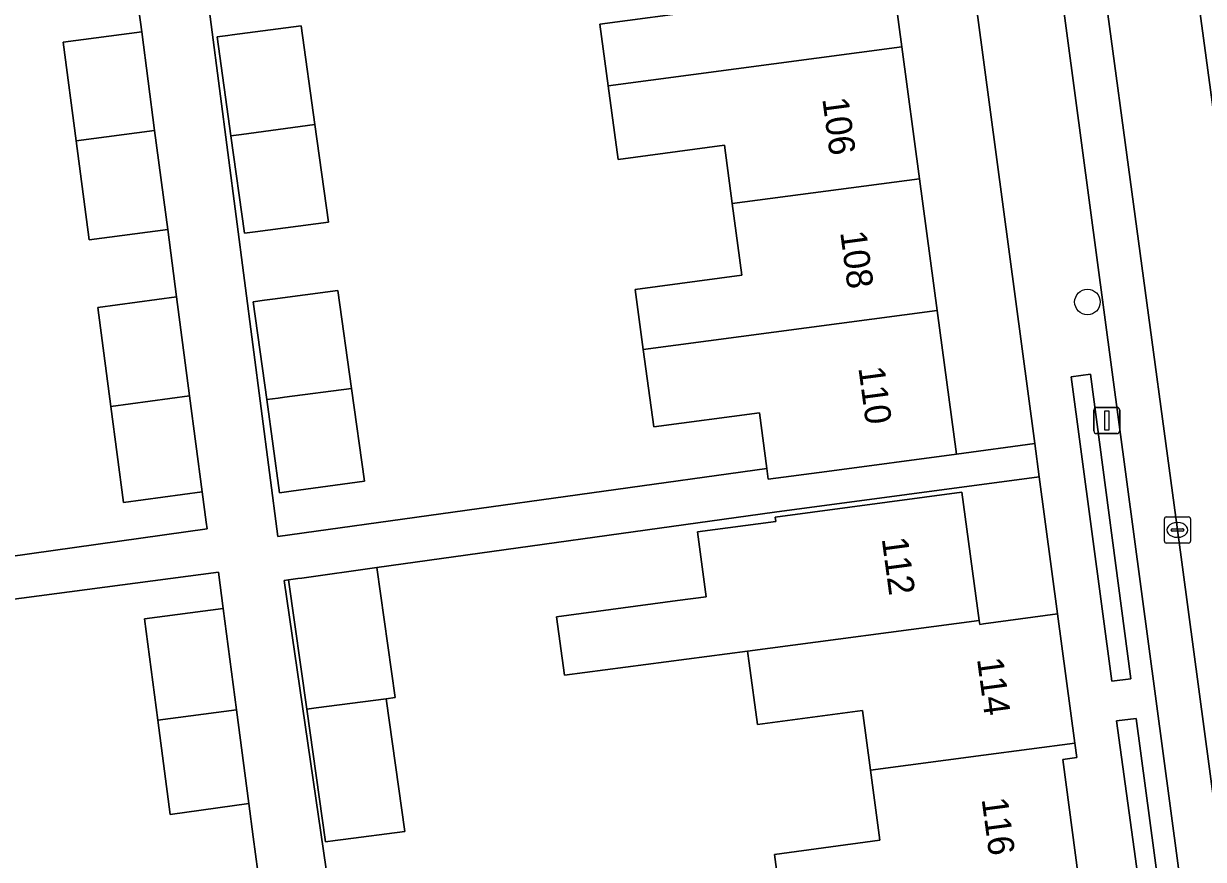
# Model space of a CAD drawing. Extents: x 163147 to 163550, y 380933 to 381639.
# Drawn here: x 163463.29 to 163508.41, y 381142.86 to 381174.85 of the extents above; entities that cross this region are included whole.
import ezdxf

# ---------------------------------------------------------------- set-up
doc = ezdxf.new("R2010")
doc.units = 0
for name, color, linetype in [('IMGEO_Boom', 7, 'Continuous'), ('IMGEO_Erf', 7, 'Continuous'), ('IMGEO_Groenvoorziening', 7, 'Continuous'), ('IMGEO_Kolk', 7, 'Continuous'), ('IMGEO_Lichtmast', 7, 'Continuous'), ('IMGEO_Pand', 7, 'Continuous'), ('IMGEO_Pand_nummerreeks', 7, 'Continuous'), ('IMGEO_Parkeervlak_open', 7, 'Continuous'), ('IMGEO_Rijbaan_lokaal_open', 7, 'Continuous'), ('IMGEO_Voetpad_open', 7, 'Continuous')]:
    doc.layers.add(name, color=color, linetype=linetype)

msp = doc.modelspace()

# ---------------------------------------------------------------- linework, layer by layer
at = {"layer": 'IMGEO_Boom'}
msp.add_circle((163503.975, 381164.194), 0.489, dxfattribs=at)
at = {"layer": 'IMGEO_Erf'}
for points in [[(163497.876, 381189.391), (163494.859, 381188.987), (163495.521, 381184.055), (163496.198, 381179.008), (163496.875, 381173.959), (163497.553, 381168.911), (163498.23, 381163.862), (163498.966, 381158.376), (163501.959, 381158.775), (163500, 381173.462)], [(163474.436, 381170.98), (163474.953, 381167.249), (163472.146, 381166.877), (163471.737, 381166.823), (163471.221, 381170.553), (163470.697, 381174.339), (163471.106, 381174.393), (163471.266, 381174.415), (163473.912, 381174.766)], [(163475.833, 381160.888), (163476.325, 381157.337), (163473.52, 381156.949), (163473.084, 381156.888), (163472.59, 381160.458), (163472.071, 381164.201), (163472.508, 381164.259), (163472.818, 381164.3), (163475.315, 381164.631)]]:
    msp.add_lwpolyline(points, close=True, dxfattribs=at)
for points in [[(163451.727, 381152.897), (163470.315, 381155.515), (163470.279, 381155.771), (163470.127, 381156.923), (163467.118, 381156.527), (163466.635, 381160.197), (163466.137, 381163.983), (163469.145, 381164.386), (163468.975, 381165.675), (163468.804, 381166.971), (163465.797, 381166.568), (163465.299, 381170.355), (163464.801, 381174.133), (163467.809, 381174.536), (163467.638, 381175.837), (163467.466, 381177.144), (163464.458, 381176.741), (163463.957, 381180.549), (163463.382, 381184.919), (163466.391, 381185.315), (163466.221, 381186.604), (163463.614, 381186.261), (163463.374, 381186.229), (163463.212, 381186.208)], [(163470.145, 381177.27), (163473.017, 381155.223), (163491.716, 381157.821), (163491.429, 381159.958), (163487.388, 381159.415), (163486.992, 381162.37), (163486.682, 381164.678), (163490.758, 381165.225), (163490.391, 381167.96), (163490.091, 381170.193), (163486.024, 381169.648), (163485.646, 381172.468), (163485.33, 381174.823), (163489.372, 381175.365)], [(163492.331, 381140.667), (163492.011, 381143.056), (163496.04, 381143.596), (163495.679, 381146.282), (163495.373, 381148.564), (163491.355, 381148.025), (163491.04, 381150.372), (163490.978, 381150.833), (163483.972, 381149.909), (163483.672, 381152.144), (163488.304, 381152.766), (163489.394, 381152.912), (163489.06, 381155.399), (163492.053, 381155.8), (163492.031, 381155.958), (163499.177, 381156.915), (163499.836, 381152.002), (163499.855, 381151.857), (163500, 381151.877), (163502.828, 381152.255), (163502.129, 381157.501), (163492.004, 381156.151), (163476.803, 381154.036), (163477.507, 381149.057), (163477.161, 381149.011), (163477.878, 381143.933), (163475.52, 381143.623), (163475.202, 381143.581), (163474.839, 381143.533), (163474.122, 381148.61), (163473.423, 381153.559), (163473.262, 381153.534), (163477.678, 381123.119)], [(163472.251, 381142.395), (163472.076, 381143.722), (163471.908, 381144.999), (163468.902, 381144.586), (163468.427, 381148.193), (163467.917, 381152.07), (163470.925, 381152.466), (163470.743, 381153.849), (163451.998, 381151.38)]]:
    msp.add_lwpolyline(points, dxfattribs=at)
at = {"layer": 'IMGEO_Groenvoorziening'}
for points in [[(163504.911, 381149.686), (163505.63, 381149.779), (163504.095, 381161.434), (163503.349, 381161.325)], [(163506.529, 381137.695), (163507.234, 381137.78), (163505.837, 381148.257), (163505.092, 381148.167)]]:
    msp.add_lwpolyline(points, close=True, dxfattribs=at)
at = {"layer": 'IMGEO_Kolk'}
for p, q in [((163506.916, 381155.044), (163506.916, 381155.896)), ((163506.991, 381155.97), (163507.843, 381155.97)), ((163507.404, 381155.75), (163507.429, 381155.75)), ((163507.917, 381155.896), (163507.917, 381155.044)), ((163507.175, 381155.464), (163507.175, 381155.476)), ((163507.613, 381155.427), (163507.215, 381155.427)), ((163507.218, 381155.513), (163507.616, 381155.513)), ((163507.427, 381155.19), (163507.402, 381155.19)), ((163507.659, 381155.476), (163507.659, 381155.464)), ((163507.843, 381154.97), (163506.991, 381154.97))]:
    msp.add_line(p, q, dxfattribs=at)
for points in [[(163506.916, 381155.044), (163506.916, 381155.896)], [(163506.991, 381155.97), (163507.843, 381155.97)], [(163507.917, 381155.896), (163507.917, 381155.044)], [(163507.843, 381154.97), (163506.991, 381154.97)]]:
    msp.add_lwpolyline(points, dxfattribs=at)
for centre, radius, start, end in [((163506.993, 381155.894), 0.0765, 91.552, 178.448), ((163506.993, 381155.894), 0.0765, 91.552, 178.448), ((163507.841, 381155.894), 0.0765, 1.552, 88.448), ((163507.841, 381155.894), 0.0765, 1.552, 88.448), ((163507.215, 381155.473), 0.0403, 85.8775, 175.7526), ((163507.212, 381155.463), 0.0366, 178.938, 274.7102), ((163507.616, 381155.47), 0.043, 264.8664, 352.4533), ((163507.62, 381155.475), 0.0386, 1.7309, 96.639), ((163506.993, 381155.046), 0.0765, 181.552, 268.448), ((163506.993, 381155.046), 0.0765, 181.552, 268.448), ((163507.841, 381155.046), 0.0765, 271.552, 358.448), ((163507.841, 381155.046), 0.0765, 271.552, 358.448)]:
    msp.add_arc(centre, radius, start, end, dxfattribs=at)
for centre, major_axis, ratio, start_param, end_param in [((163507.403, 381155.47), (-0.387, 0.002), 0.722429, 4.712389, 7.853982), ((163507.428, 381155.47), (-0.39, 0.002), 0.717154, 1.570796, 4.712389)]:
    msp.add_ellipse(centre, major_axis=major_axis, ratio=ratio, start_param=start_param, end_param=end_param, dxfattribs=at)
at = {"layer": 'IMGEO_Lichtmast'}
for p, q in [((163504.318, 381160.159), (163505.108, 381160.159)), ((163505.108, 381160.159), (163504.318, 381160.159)), ((163504.218, 381159.259), (163504.218, 381160.059)), ((163504.218, 381160.059), (163504.218, 381159.259)), ((163505.208, 381160.059), (163505.208, 381159.259)), ((163505.208, 381159.259), (163505.208, 381160.059)), ((163505.108, 381159.159), (163504.318, 381159.159)), ((163504.318, 381159.159), (163505.108, 381159.159))]:
    msp.add_line(p, q, dxfattribs=at)
msp.add_lwpolyline([(163504.638, 381160.034), (163504.788, 381160.034), (163504.788, 381159.284), (163504.638, 381159.284), (163504.638, 381160.034)], dxfattribs=at)
for centre, start, end in [((163504.318, 381160.059), 90, 180), ((163504.318, 381160.059), 90, 180), ((163505.108, 381160.059), 0, 90), ((163505.108, 381160.059), 360, 90), ((163504.318, 381159.259), 180, 270), ((163504.318, 381159.259), 180, 270), ((163505.108, 381159.259), 270, 0), ((163505.108, 381159.259), 270, 0)]:
    msp.add_arc(centre, 0.1, start, end, dxfattribs=at)
at = {"layer": 'IMGEO_Pand'}
for points in [[(163496.198, 381179.008), (163489.011, 381178.053), (163489.372, 381175.365), (163485.33, 381174.823), (163485.646, 381172.468), (163496.875, 381173.959)], [(163467.809, 381174.536), (163464.801, 381174.133), (163465.299, 381170.355), (163468.306, 381170.759)], [(163471.221, 381170.553), (163471.63, 381170.607), (163471.913, 381170.645), (163474.436, 381170.98), (163473.912, 381174.766), (163471.266, 381174.415), (163471.106, 381174.393), (163470.697, 381174.339)], [(163496.875, 381173.959), (163485.646, 381172.468), (163486.024, 381169.648), (163490.091, 381170.193), (163490.391, 381167.96), (163497.553, 381168.911)], [(163474.436, 381170.98), (163471.913, 381170.645), (163471.63, 381170.607), (163471.221, 381170.553), (163471.737, 381166.823), (163472.146, 381166.877), (163474.953, 381167.249)], [(163468.306, 381170.759), (163465.299, 381170.355), (163465.797, 381166.568), (163468.804, 381166.971)], [(163497.553, 381168.911), (163490.391, 381167.96), (163490.758, 381165.225), (163486.682, 381164.678), (163486.992, 381162.37), (163498.23, 381163.862)], [(163472.59, 381160.458), (163473.027, 381160.516), (163473.272, 381160.548), (163475.833, 381160.888), (163475.315, 381164.631), (163472.818, 381164.3), (163472.508, 381164.259), (163472.071, 381164.201)], [(163469.145, 381164.386), (163466.137, 381163.983), (163466.635, 381160.197), (163469.643, 381160.604)], [(163498.23, 381163.862), (163486.992, 381162.37), (163487.388, 381159.415), (163491.429, 381159.958), (163491.716, 381157.821), (163491.771, 381157.41), (163494.011, 381157.711), (163498.966, 381158.376)], [(163469.643, 381160.604), (163466.635, 381160.197), (163467.118, 381156.527), (163470.127, 381156.923)], [(163475.833, 381160.888), (163473.272, 381160.548), (163473.027, 381160.516), (163472.59, 381160.458), (163473.084, 381156.888), (163473.52, 381156.949), (163476.325, 381157.337)], [(163499.177, 381156.915), (163492.031, 381155.958), (163492.053, 381155.8), (163489.06, 381155.399), (163489.394, 381152.912), (163488.304, 381152.766), (163483.672, 381152.144), (163483.972, 381149.909), (163490.978, 381150.833), (163499.836, 381152.002)], [(163476.803, 381154.036), (163473.929, 381153.63), (163473.785, 381153.61), (163473.423, 381153.559), (163474.122, 381148.61), (163474.485, 381148.658), (163477.161, 381149.011), (163477.507, 381149.057)], [(163470.925, 381152.466), (163467.917, 381152.07), (163468.427, 381148.193), (163471.437, 381148.582)], [(163502.828, 381152.255), (163500, 381151.877), (163499.855, 381151.857), (163499.836, 381152.002), (163490.978, 381150.833), (163491.04, 381150.372), (163491.355, 381148.025), (163495.373, 381148.564), (163495.679, 381146.282), (163500, 381146.852), (163503.491, 381147.312)], [(163477.161, 381149.011), (163474.485, 381148.658), (163474.122, 381148.61), (163474.839, 381143.533), (163475.202, 381143.581), (163475.52, 381143.623), (163477.878, 381143.933)], [(163471.437, 381148.582), (163468.427, 381148.193), (163468.902, 381144.586), (163471.908, 381144.999)], [(163503.638, 381142.159), (163503.03, 381146.692), (163503.564, 381146.764), (163503.491, 381147.312), (163500, 381146.852), (163495.679, 381146.282), (163496.04, 381143.596), (163492.011, 381143.056), (163492.331, 381140.667), (163500, 381141.679)]]:
    msp.add_lwpolyline(points, close=True, dxfattribs=at)
at = {"layer": 'IMGEO_Parkeervlak_open'}
for points in [[(163503.796, 381208.674), (163504.806, 381200.993), (163506.998, 381184.771), (163507.648, 381179.955), (163510.87, 381156.109), (163513.587, 381135.867), (163514.789, 381126.831), (163514.8, 381126.75), (163516.355, 381126.983)], [(163507.418, 381155.47), (163504.439, 381177.585), (163504.184, 381179.487), (163503.88, 381181.755)], [(163502.646, 381178.504), (163511.092, 381115.35)], [(163513.15, 381112.822), (163512.657, 381116.312), (163510.084, 381135.559), (163507.418, 381155.47)]]:
    msp.add_lwpolyline(points, dxfattribs=at)
at = {"layer": 'IMGEO_Rijbaan_lokaal_open'}
msp.add_lwpolyline([(163514.8, 381126.75), (163514.789, 381126.831), (163513.587, 381135.867), (163510.87, 381156.109), (163507.648, 381179.955), (163504.184, 381179.487), (163504.439, 381177.585), (163507.418, 381155.47), (163510.084, 381135.559), (163512.657, 381116.312), (163513.15, 381112.822), (163513.165, 381112.719), (163513.181, 381112.606), (163513.54, 381109.521), (163515.019, 381109.754), (163516.743, 381110.026), (163514.166, 381126.655)], close=True, dxfattribs=at)
at = {"layer": 'IMGEO_Voetpad_open'}
for points in [[(163493.605, 381221.412), (163497.667, 381190.955), (163497.876, 381189.391), (163500, 381173.462), (163501.959, 381158.775), (163502.129, 381157.501), (163502.828, 381152.255), (163503.491, 381147.312), (163503.564, 381146.764), (163503.03, 381146.692), (163503.638, 381142.159), (163504.321, 381137.076), (163504.344, 381136.902), (163504.857, 381136.97), (163505.516, 381132.062), (163505.582, 381131.571), (163506.211, 381126.885), (163506.428, 381125.265), (163506.464, 381125), (163506.904, 381121.729), (163507.962, 381114.2), (163509.388, 381104.055), (163509.963, 381099.962)], [(163463.206, 381209.156), (163463.379, 381207.842), (163463.548, 381206.555), (163464.047, 381202.766), (163464.546, 381198.975), (163464.716, 381197.682), (163465.215, 381193.888), (163465.384, 381192.603), (163466.221, 381186.604), (163466.391, 381185.315), (163466.964, 381180.957), (163467.466, 381177.144), (163467.638, 381175.837), (163467.809, 381174.536), (163468.306, 381170.759), (163468.804, 381166.971), (163468.975, 381165.675), (163469.145, 381164.386), (163469.643, 381160.604), (163470.127, 381156.923), (163470.279, 381155.771), (163470.315, 381155.515), (163451.727, 381152.897)], [(163511.092, 381115.35), (163502.646, 381178.504)], [(163477.678, 381123.119), (163473.262, 381153.534), (163473.423, 381153.559), (163473.785, 381153.61), (163473.929, 381153.63), (163476.803, 381154.036), (163492.004, 381156.151), (163502.129, 381157.501), (163501.959, 381158.775), (163498.966, 381158.376), (163494.011, 381157.711), (163491.771, 381157.41), (163491.716, 381157.821), (163473.017, 381155.223), (163470.145, 381177.27)], [(163451.998, 381151.38), (163470.743, 381153.849), (163470.925, 381152.466), (163471.437, 381148.582), (163471.908, 381144.999), (163472.076, 381143.722), (163472.251, 381142.395)]]:
    msp.add_lwpolyline(points, dxfattribs=at)
for points in [[(163505.63, 381149.779), (163504.911, 381149.686), (163503.349, 381161.325), (163504.095, 381161.434)], [(163506.529, 381137.695), (163505.092, 381148.167), (163505.837, 381148.257), (163507.234, 381137.78)]]:
    msp.add_lwpolyline(points, close=True, dxfattribs=at)

# ---------------------------------------------------------------- texts
at = {"layer": 'IMGEO_Pand_nummerreeks'}
for s, rotation, p in [('106', 277.6416, (163493.833, 381171.97)), ('108', 277.6416, (163494.517, 381166.864)), ('110', 277.643, (163495.214, 381161.673)), ('112', 277.6373, (163496.106, 381155.139)), ('114', 277.6259, (163499.75, 381150.534)), ('116', 277.6393, (163499.925, 381145.175))]:
    msp.add_text(s, height=1, rotation=rotation, dxfattribs=at).set_placement(p)

doc.saveas('drawing.dxf')
